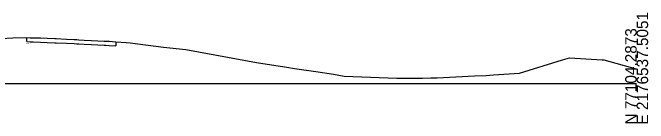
# Model space of a CAD drawing. Extents: x 2207892 to 2209721, y 61220 to 65449.
# Drawn here: x 2208165.8 to 2208321, y 61897.6 to 61924.6 of the extents above; entities that cross this region are included whole.
import ezdxf

# ---------------------------------------------------------------- set-up
doc = ezdxf.new("R2010")
doc.units = 0
for name, color, linetype in [('Exist DTM Drainline Cogo Comment', 7, 'Continuous'), ('Exist Roads EOP Other Cogo Elevation', 7, 'Continuous'), ('Exist Roads EOP Other Cogo Number', 7, 'Continuous'), ('Exist Structure Minor Head and End Wall Cogo Point CELL', 7, 'Continuous')]:
    doc.layers.add(name, color=color, linetype=linetype)

msp = doc.modelspace()

# ---------------------------------------------------------------- linework, layer by layer
at = {"layer": 'Exist DTM Drainline Cogo Comment'}
for p, q in [((2208169.25, 61917.55), (2208169.25, 61918.55)), ((2208169.25, 61917.55), (2208170.04, 61917.52)), ((2208169.25, 61917.55), (2208169.25, 61917.55)), ((2208170.04, 61917.52), (2208170.81, 61917.5)), ((2208170.81, 61917.5), (2208172.56, 61917.44)), ((2208172.56, 61917.44), (2208174.21, 61917.38)), ((2208174.21, 61917.38), (2208176.09, 61917.29)), ((2208176.09, 61917.29), (2208176.44, 61917.28)), ((2208176.44, 61917.28), (2208178.9, 61917.16)), ((2208178.9, 61917.16), (2208180.79, 61917.07)), ((2208180.79, 61917.07), (2208181.48, 61917.04)), ((2208181.48, 61917.04), (2208181.97, 61917.01)), ((2208181.97, 61917.01), (2208183.28, 61916.95)), ((2208183.28, 61916.95), (2208185.07, 61916.86)), ((2208185.07, 61916.86), (2208188.15, 61916.7)), ((2208188.15, 61916.7), (2208188.53, 61916.68)), ((2208188.53, 61916.68), (2208189.32, 61916.63)), ((2208189.32, 61916.63), (2208190.99, 61916.54)), ((2208190.99, 61917.54), (2208190.99, 61916.54))]:
    msp.add_line(p, q, dxfattribs=at)
at = {"layer": 'Exist Roads EOP Other Cogo Elevation'}
msp.add_lwpolyline([(2208161.34, 61918.27), (2208165.84, 61918.45), (2208169.25, 61918.55), (2208170.04, 61918.52), (2208170.81, 61918.5), (2208172.56, 61918.44), (2208174.21, 61918.38), (2208176.09, 61918.29), (2208176.44, 61918.28), (2208178.9, 61918.16), (2208180.79, 61918.07), (2208181.48, 61918.04), (2208181.97, 61918.01), (2208183.28, 61917.95), (2208185.07, 61917.86), (2208188.15, 61917.7), (2208188.53, 61917.68), (2208189.32, 61917.63), (2208190.99, 61917.54), (2208193.5, 61917.35), (2208194.51, 61917.28), (2208202.59, 61916.21), (2208208.04, 61915.61), (2208225.33, 61912.46), (2208231.14, 61911.53), (2208232.74, 61911.28), (2208234.65, 61911.02), (2208239.83, 61910.3), (2208244.15, 61909.6), (2208246.77, 61909.15), (2208259.62, 61908.66), (2208265.84, 61908.65), (2208267.92, 61908.69), (2208269.44, 61908.72), (2208278.55, 61909.19), (2208281.39, 61909.32), (2208283.19, 61909.42), (2208289.53, 61909.82), (2208300.08, 61913.12), (2208301.74, 61913.63), (2208309.79, 61913.12), (2208310.15, 61913.1), (2208318.04, 61910.94), (2208318.17, 61910.93)], dxfattribs=at)
at = {"layer": 'Exist Roads EOP Other Cogo Number'}
msp.add_line((2208118.17, 61907.31), (2208318.17, 61907.31), dxfattribs=at)

# ---------------------------------------------------------------- texts
for s, p in [('E 2176537.5051', (2208320.97, 61897.31)), ('N 77104.2873', (2208318.17, 61897.31))]:
    msp.add_text(s, height=2.8, rotation=90, dxfattribs=at).set_placement(p)
at = {"layer": 'Exist Structure Minor Head and End Wall Cogo Point CELL'}
for s, p in [('RT_Slope_Cut', (2208174.55, 61918.29)), ('RT_SS_Ditch_Base_Out', (2208169.07, 61917.01))]:
    msp.add_text(s, height=0.1, dxfattribs=at).set_placement(p)

doc.saveas('drawing.dxf')
